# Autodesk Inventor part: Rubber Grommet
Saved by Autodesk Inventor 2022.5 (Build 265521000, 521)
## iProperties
Created: 2025-02
Part Number: Rubber Grommet
Material: Generic
Document SubType Name: Modeling
Designer: AdminForWorker
Density: 1 g/cm^3
Appearance: Default
Title: Rubber Grommet
Author: AdminForWorker
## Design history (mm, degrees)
feature "Rubber Grommet"
body "Solid1"
